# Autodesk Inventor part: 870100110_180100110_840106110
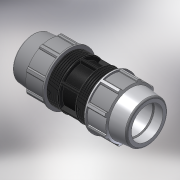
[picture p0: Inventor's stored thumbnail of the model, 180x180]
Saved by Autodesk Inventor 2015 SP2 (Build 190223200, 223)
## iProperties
Created: 2017-02
Part Number: 870100110_180100110_840106110
Material: Generic
Description: PLASSON COUPLER 110-110
Document SubType Name: Modeling
Designer: KIM
Mass: 3885.53 g
Surface Area: 4713.66 cm^2
Volume: 3885.53 cm^3
Density: 1 g/cm^3
Appearance: Default
Author: KIM
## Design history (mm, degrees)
derived "87010.ipt"
feature "Solid1::87010.ipt"
tag "TaggingFeature1"
body "Solid1"
other parameters: "d1" = 398, "d4" = 33.16667, "d5" = 56.85714, "d7" = 181, "d8" = 135.75, "d9" = 56.85714, "d11" = 5.68571, "d12" = 144.8, "d13" = 120 deg, "d14" = 143, "d15" = 6 deg, "d16" = 162.9, "d18" = 5.5, "d19" = 35 deg, "d20" = 17.5 deg, "d21" = 168.33, "d23" = 0, "d25" = 360 deg, "d27" = 3.62, "d33" = 2.2, "d34" = 9.05, "d36" = 0, "d37" = 2.2, "d38" = 2.2, "d40" = 360 deg, "d42" = 71.64, "d46" = 3.3, "d50" = 4.975, "d51" = 0, "d53" = 3.63886, "d54" = 3.63886, "d57" = 7.27771, "d62" = 159.642, "d64" = 99, "d65" = 196, "E_" = 181, "H_" = 398, "l_" = 196, "d52" = 36.38857
